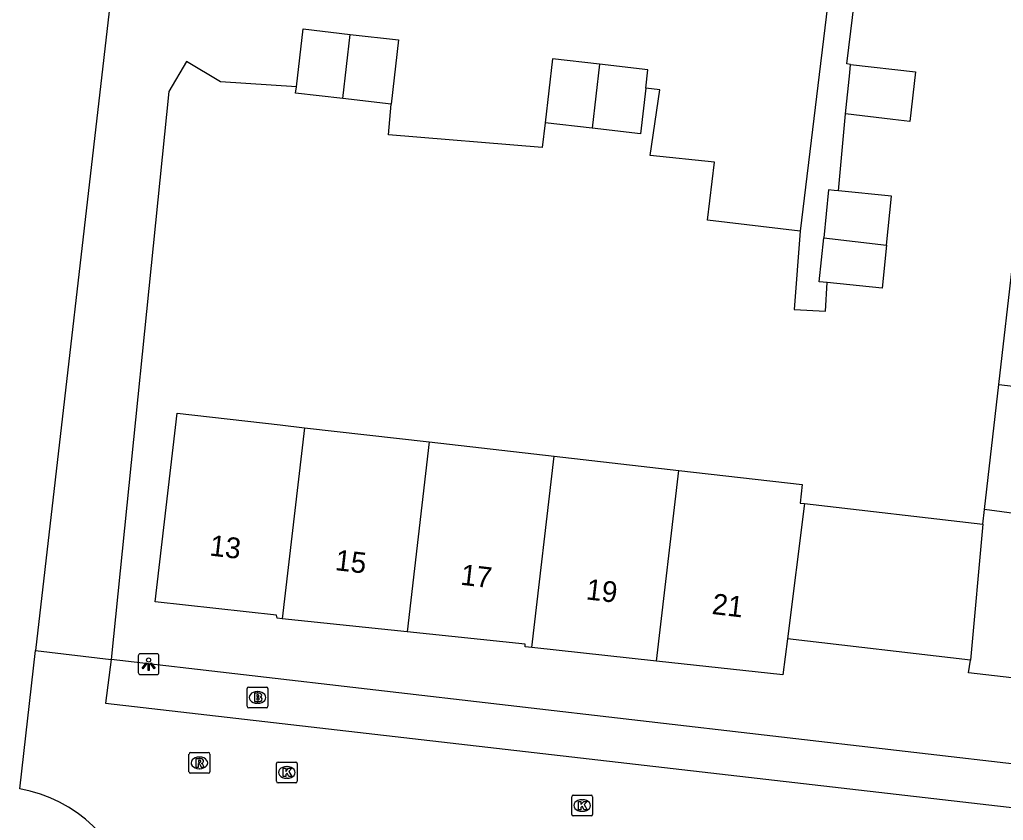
# Model space of a CAD drawing. Extents: x 161243 to 161752, y 384138 to 384885.
# Drawn here: x 161332.13 to 161379.47, y 384430.73 to 384469.29 of the extents above; entities that cross this region are included whole.
import ezdxf

# ---------------------------------------------------------------- set-up
doc = ezdxf.new("R2010")
doc.units = 0
for name, color, linetype in [('IMGEO_Brandkraan', 7, 'Continuous'), ('IMGEO_Kolk', 7, 'Continuous'), ('IMGEO_Lichtpunt', 7, 'Continuous'), ('IMGEO_Pand', 7, 'Continuous'), ('IMGEO_Pand_nummerreeks', 7, 'Continuous'), ('IMGEO_Rijbaan_lokaal_open', 7, 'Continuous'), ('IMGEO_Rioolput', 7, 'Continuous'), ('IMGEO_Voetpad_open', 7, 'Continuous')]:
    doc.layers.add(name, color=color, linetype=linetype)

msp = doc.modelspace()

# ---------------------------------------------------------------- linework, layer by layer
at = {"layer": 'IMGEO_Brandkraan'}
for p, q in [((161343.08, 384436.224), (161343.08, 384437.076)), ((161343.155, 384437.15), (161344.007, 384437.15)), ((161343.568, 384436.93), (161343.593, 384436.93)), ((161344.081, 384437.076), (161344.081, 384436.224)), ((161343.591, 384436.37), (161343.566, 384436.37)), ((161344.007, 384436.15), (161343.155, 384436.15))]:
    msp.add_line(p, q, dxfattribs=at)
for points in [[(161343.08, 384436.224), (161343.08, 384437.076)], [(161343.155, 384437.15), (161344.007, 384437.15)], [(161343.428, 384436.85), (161343.428, 384436.45), (161343.641, 384436.45)], [(161343.659, 384436.85), (161343.428, 384436.85)], [(161344.081, 384437.076), (161344.081, 384436.224)], [(161343.607, 384436.769), (161343.553, 384436.769), (161343.553, 384436.693)], [(161343.553, 384436.693), (161343.606, 384436.693)], [(161343.615, 384436.617), (161343.553, 384436.617), (161343.553, 384436.536)], [(161343.553, 384436.536), (161343.615, 384436.536)], [(161344.007, 384436.15), (161343.155, 384436.15)]]:
    msp.add_lwpolyline(points, dxfattribs=at)
for centre, radius, start, end in [((161343.157, 384437.074), 0.0765, 91.552, 178.448), ((161343.157, 384437.074), 0.0765, 91.552, 178.448), ((161343.663, 384436.705), 0.145, 59.4692, 91.5367), ((161343.688, 384436.752), 0.0922, 285.5137, 58.1501), ((161344.005, 384437.074), 0.0765, 1.552, 88.448), ((161344.005, 384437.074), 0.0765, 1.552, 88.448), ((161343.608, 384436.731), 0.0379, 267.8285, 90.9355), ((161343.616, 384436.576), 0.0404, 269.8759, 90.5077), ((161343.647, 384436.701), 0.251, 268.6676, 293.5347), ((161343.693, 384436.56), 0.105, 301.3115, 78.989), ((161343.157, 384436.226), 0.0765, 181.552, 268.448), ((161343.157, 384436.226), 0.0765, 181.552, 268.448), ((161344.005, 384436.226), 0.0765, 271.552, 358.448), ((161344.005, 384436.226), 0.0765, 271.552, 358.448)]:
    msp.add_arc(centre, radius, start, end, dxfattribs=at)
for centre, major_axis, ratio, start_param, end_param in [((161343.567, 384436.65), (-0.387, 0.002), 0.722429, 4.712389, 7.853982), ((161343.592, 384436.65), (-0.39, 0.002), 0.717154, 1.570796, 4.712389)]:
    msp.add_ellipse(centre, major_axis=major_axis, ratio=ratio, start_param=start_param, end_param=end_param, dxfattribs=at)
at = {"layer": 'IMGEO_Kolk'}
for p, q in [((161344.491, 384432.612), (161344.491, 384433.464)), ((161344.566, 384433.538), (161345.418, 384433.538)), ((161345.492, 384433.464), (161345.492, 384432.612)), ((161344.979, 384433.318), (161345.004, 384433.318)), ((161345.418, 384432.538), (161344.566, 384432.538)), ((161345.002, 384432.758), (161344.977, 384432.758)), ((161358.701, 384431.02), (161358.701, 384431.872)), ((161358.776, 384431.946), (161359.628, 384431.946)), ((161359.189, 384431.726), (161359.214, 384431.726)), ((161359.702, 384431.872), (161359.702, 384431.02)), ((161359.212, 384431.166), (161359.187, 384431.166)), ((161359.628, 384430.946), (161358.776, 384430.946))]:
    msp.add_line(p, q, dxfattribs=at)
for points in [[(161344.491, 384432.612), (161344.491, 384433.464)], [(161344.566, 384433.538), (161345.418, 384433.538)], [(161345.492, 384433.464), (161345.492, 384432.612)], [(161344.812, 384433.238), (161344.935, 384433.238), (161344.935, 384433.087), (161345.065, 384433.238), (161345.229, 384433.238), (161345.083, 384433.087), (161345.236, 384432.838), (161345.084, 384432.838), (161344.999, 384433.002), (161344.935, 384432.935), (161344.935, 384432.838), (161344.812, 384432.838), (161344.812, 384433.238)], [(161345.418, 384432.538), (161344.566, 384432.538)], [(161358.701, 384431.02), (161358.701, 384431.872)], [(161358.776, 384431.946), (161359.628, 384431.946)], [(161359.022, 384431.646), (161359.145, 384431.646), (161359.145, 384431.495), (161359.275, 384431.646), (161359.439, 384431.646), (161359.293, 384431.495), (161359.446, 384431.246), (161359.294, 384431.246), (161359.209, 384431.41), (161359.145, 384431.343), (161359.145, 384431.246), (161359.022, 384431.246), (161359.022, 384431.646)], [(161359.702, 384431.872), (161359.702, 384431.02)], [(161359.628, 384430.946), (161358.776, 384430.946)]]:
    msp.add_lwpolyline(points, dxfattribs=at)
for centre, start, end in [((161344.568, 384433.462), 91.552, 178.448), ((161344.568, 384433.462), 91.552, 178.448), ((161345.416, 384433.462), 1.552, 88.448), ((161345.416, 384433.462), 1.552, 88.448), ((161344.568, 384432.614), 181.552, 268.448), ((161344.568, 384432.614), 181.552, 268.448), ((161345.416, 384432.614), 271.552, 358.448), ((161345.416, 384432.614), 271.552, 358.448), ((161358.778, 384431.87), 91.552, 178.448), ((161358.778, 384431.87), 91.552, 178.448), ((161359.626, 384431.87), 1.552, 88.448), ((161359.626, 384431.87), 1.552, 88.448), ((161358.778, 384431.022), 181.552, 268.448), ((161358.778, 384431.022), 181.552, 268.448), ((161359.626, 384431.022), 271.552, 358.448), ((161359.626, 384431.022), 271.552, 358.448)]:
    msp.add_arc(centre, 0.0765, start, end, dxfattribs=at)
for centre, major_axis, ratio, start_param, end_param in [((161344.978, 384433.038), (-0.387, 0.002), 0.722429, 4.712389, 7.853982), ((161345.003, 384433.038), (-0.39, 0.002), 0.717154, 1.570796, 4.712389), ((161359.188, 384431.446), (-0.387, 0.002), 0.722429, 4.712389, 7.853982), ((161359.213, 384431.446), (-0.39, 0.002), 0.717154, 1.570796, 4.712389)]:
    msp.add_ellipse(centre, major_axis=major_axis, ratio=ratio, start_param=start_param, end_param=end_param, dxfattribs=at)
at = {"layer": 'IMGEO_Lichtpunt'}
for p, q in [((161338.739, 384438.751), (161337.931, 384438.751)), ((161338.739, 384438.751), (161337.931, 384438.751)), ((161337.837, 384438.656), (161337.837, 384437.849)), ((161337.837, 384438.656), (161337.837, 384437.849)), ((161338.833, 384437.849), (161338.833, 384438.656)), ((161338.833, 384437.849), (161338.833, 384438.656)), ((161337.931, 384437.755), (161338.739, 384437.755)), ((161337.931, 384437.755), (161338.739, 384437.755))]:
    msp.add_line(p, q, dxfattribs=at)
for points in [[(161338.211, 384438.32), (161338.25, 384438.292), (161338.062, 384438.03), (161338.024, 384438.057), (161338.211, 384438.32)], [(161338.313, 384438.272), (161338.36, 384438.272), (161338.36, 384437.95), (161338.313, 384437.95), (161338.313, 384438.272)], [(161338.423, 384438.292), (161338.461, 384438.319), (161338.648, 384438.057), (161338.609, 384438.029), (161338.423, 384438.292)]]:
    msp.add_lwpolyline(points, dxfattribs=at)
msp.add_circle((161338.336, 384438.454), 0.0994, dxfattribs=at)
for centre, start, end in [((161337.931, 384438.656), 90, 180), ((161337.931, 384438.656), 90, 180), ((161338.739, 384438.656), 0, 90), ((161338.739, 384438.656), 0, 90), ((161337.931, 384437.849), 180, 270), ((161337.931, 384437.849), 180, 270), ((161338.739, 384437.849), 270, 0), ((161338.739, 384437.849), 270, 360)]:
    msp.add_arc(centre, 0.0946, start, end, dxfattribs=at)
at = {"layer": 'IMGEO_Pand'}
for points in [[(161345.447, 384466.051), (161345.771, 384468.848), (161348.036, 384468.585)], [(161347.677, 384465.495), (161348.036, 384468.585)], [(161348.036, 384468.585), (161350.361, 384468.316), (161350.003, 384465.226)], [(161360.042, 384467.15), (161357.775, 384467.413), (161357.417, 384464.321)], [(161360.042, 384467.15), (161359.683, 384464.059)], [(161362.262, 384465.992), (161362.365, 384466.881), (161360.042, 384467.15)], [(161371.88, 384464.756), (161372.078, 384466.736), (161372.118, 384467.138)], [(161372.118, 384467.138), (161375.247, 384466.773), (161374.97, 384464.395), (161374.149, 384464.491), (161371.88, 384464.756)], [(161347.677, 384465.495), (161345.413, 384465.757), (161345.447, 384466.051)], [(161362.262, 384465.992), (161362.007, 384463.791), (161359.683, 384464.059)], [(161350.003, 384465.226), (161347.677, 384465.495)], [(161359.683, 384464.059), (161357.417, 384464.321)], [(161371.54, 384461.05), (161371.333, 384461.071), (161371.057, 384461.099), (161370.826, 384458.79)], [(161373.851, 384458.437), (161374.086, 384460.796), (161371.54, 384461.05)], [(161370.993, 384456.632), (161370.614, 384456.67), (161370.826, 384458.79)], [(161370.826, 384458.79), (161373.851, 384458.437)], [(161373.851, 384458.437), (161373.644, 384456.367), (161370.993, 384456.632)], [(161379.251, 384451.718), (161379.938, 384457.726)], [(161378.564, 384445.707), (161379.251, 384451.718)], [(161379.251, 384451.718), (161388.569, 384450.629)], [(161344.766, 384440.439), (161344.517, 384440.465), (161344.488, 384440.607), (161338.658, 384441.253), (161339.706, 384450.341), (161344.671, 384449.773), (161345.835, 384449.64)], [(161345.835, 384449.64), (161344.766, 384440.439)], [(161345.835, 384449.64), (161351.84, 384448.953)], [(161351.84, 384448.953), (161350.778, 384439.813)], [(161351.84, 384448.953), (161357.847, 384448.267)], [(161356.775, 384439.05), (161357.847, 384448.267)], [(161357.847, 384448.267), (161363.852, 384447.58)], [(161362.785, 384438.397), (161363.852, 384447.58)], [(161363.852, 384447.58), (161369.792, 384446.901), (161369.69, 384446.007), (161369.897, 384445.983)], [(161369.897, 384445.983), (161369.09, 384439.476)], [(161369.897, 384445.983), (161378.483, 384445.002)], [(161378.483, 384445.002), (161378.564, 384445.707)], [(161385.125, 384444.814), (161378.564, 384445.707)], [(161378.483, 384445.002), (161377.895, 384438.441)], [(161385.125, 384444.814), (161384.202, 384437.09), (161377.798, 384437.835), (161377.895, 384438.441)], [(161350.778, 384439.813), (161344.766, 384440.439)], [(161356.775, 384439.05), (161356.462, 384439.084), (161356.461, 384439.222), (161350.778, 384439.813)], [(161369.09, 384439.476), (161368.854, 384437.737), (161362.785, 384438.397)], [(161377.895, 384438.441), (161369.09, 384439.476)], [(161362.785, 384438.397), (161356.775, 384439.05)]]:
    msp.add_lwpolyline(points, dxfattribs=at)
at = {"layer": 'IMGEO_Rijbaan_lokaal_open'}
for points in [[(161371.732, 384475.931), (161369.687, 384459.099)], [(161336.946, 384474.139), (161336.632, 384471.394), (161332.897, 384438.907)], [(161345.447, 384466.051), (161341.804, 384466.297), (161340.159, 384467.275), (161339.305, 384465.833), (161336.535, 384438.485)], [(161369.687, 384459.099), (161365.23, 384459.635), (161365.566, 384462.431), (161362.481, 384462.751), (161362.947, 384465.913), (161362.262, 384465.992)], [(161357.417, 384464.321), (161357.28, 384463.143), (161349.875, 384463.751), (161350.003, 384465.226)], [(161332.131, 384432.245), (161332.897, 384438.907)], [(161332.897, 384438.907), (161336.535, 384438.485)], [(161336.535, 384438.485), (161336.257, 384436.376), (161382.402, 384431.06), (161401.922, 384428.768)]]:
    msp.add_lwpolyline(points, dxfattribs=at)
msp.add_arc((161331.055, 384425.741), 6.592, 10.7616, 80.6019, dxfattribs=at)
at = {"layer": 'IMGEO_Rioolput'}
for p, q in [((161340.355, 384434), (161341.207, 384434)), ((161340.28, 384433.074), (161340.28, 384433.926)), ((161340.768, 384433.78), (161340.793, 384433.78)), ((161341.281, 384433.926), (161341.281, 384433.074)), ((161341.207, 384433), (161340.355, 384433)), ((161340.791, 384433.22), (161340.766, 384433.22))]:
    msp.add_line(p, q, dxfattribs=at)
for points in [[(161340.355, 384434), (161341.207, 384434)], [(161340.28, 384433.074), (161340.28, 384433.926)], [(161340.869, 384433.698), (161340.617, 384433.7), (161340.617, 384433.3)], [(161340.617, 384433.3), (161340.741, 384433.3), (161340.741, 384433.462), (161340.752, 384433.462)], [(161340.795, 384433.619), (161340.741, 384433.619), (161340.741, 384433.538)], [(161340.741, 384433.538), (161340.793, 384433.538)], [(161341.281, 384433.926), (161341.281, 384433.074)], [(161341.207, 384433), (161340.355, 384433)], [(161340.799, 384433.433), (161340.87, 384433.3), (161341.01, 384433.3), (161340.945, 384433.426)]]:
    msp.add_lwpolyline(points, dxfattribs=at)
for centre, radius, start, end in [((161340.357, 384433.924), 0.0765, 91.552, 178.448), ((161340.357, 384433.924), 0.0765, 91.552, 178.448), ((161341.205, 384433.924), 0.0765, 1.552, 88.448), ((161341.205, 384433.924), 0.0765, 1.552, 88.448), ((161340.751, 384433.409), 0.0533, 26.0293, 88.6989), ((161340.777, 384433.727), 0.19, 274.7715, 282.9687), ((161340.801, 384433.523), 0.0964, 77.0061, 93.1865), ((161340.815, 384433.58), 0.0378, 276.6634, 79.6772), ((161340.868, 384433.588), 0.109, 350.3612, 89.416), ((161340.866, 384433.588), 0.112, 277.5842, 350.9817), ((161340.85, 384433.373), 0.108, 29.5134, 73.7905), ((161340.357, 384433.076), 0.0765, 181.552, 268.448), ((161340.357, 384433.076), 0.0765, 181.552, 268.448), ((161341.205, 384433.076), 0.0765, 271.552, 358.448), ((161341.205, 384433.076), 0.0765, 271.552, 358.448)]:
    msp.add_arc(centre, radius, start, end, dxfattribs=at)
for centre, major_axis, ratio, start_param, end_param in [((161340.767, 384433.5), (-0.387, 0.002), 0.722429, 4.712389, 7.853982), ((161340.792, 384433.5), (-0.39, 0.002), 0.717154, 1.570796, 4.712389)]:
    msp.add_ellipse(centre, major_axis=major_axis, ratio=ratio, start_param=start_param, end_param=end_param, dxfattribs=at)
at = {"layer": 'IMGEO_Voetpad_open'}
for points in [[(161372.118, 384467.138), (161371.946, 384467.158), (161372.872, 384474.797)], [(161371.54, 384461.05), (161371.88, 384464.756)], [(161369.687, 384459.099), (161369.398, 384455.338), (161370.917, 384455.254), (161370.993, 384456.632)], [(161387.488, 384432.576), (161336.535, 384438.485)]]:
    msp.add_lwpolyline(points, dxfattribs=at)

# ---------------------------------------------------------------- texts
at = {"layer": 'IMGEO_Pand_nummerreeks'}
for s, p in [('13', (161341.239, 384443.489)), ('15', (161347.278, 384442.786)), ('17', (161353.317, 384442.083)), ('19', (161359.357, 384441.379)), ('21', (161365.417, 384440.674))]:
    msp.add_text(s, height=1, rotation=353.3584, dxfattribs=at).set_placement(p)

doc.saveas('drawing.dxf')
